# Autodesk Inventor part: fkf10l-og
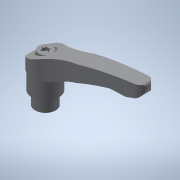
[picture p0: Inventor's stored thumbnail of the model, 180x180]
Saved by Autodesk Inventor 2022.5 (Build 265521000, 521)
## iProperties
Created: 2017-09
Part Number: fkf10l-og
Material: 一般
Document SubType Name: Modeling
Designer: imaocorp
Density: 1 g/cm^3
Appearance: 既定
Author: imaocorp
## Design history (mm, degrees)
node "fkf10l-og.x_t1"
node "fkf10l-og"
node "Base1"
